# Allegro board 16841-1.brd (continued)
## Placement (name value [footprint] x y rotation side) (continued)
C7810  SC1U50V3KX-GP  [C603H32]  165.25 103.59 90 top
C7811  SC1U50V3KX-GP  [C603H32]  165.25 105.62 90 top
C7812  SC1U50V3KX-GP  [C603H32]  160.42 121.5 180 top
C7813  SC10U6D3V3MX-GP  [C603H38]  169.06 112.51 270 top
C7814  SC1U50V3KX-GP  [C603H32]  169.06 107.18 270 top
C7815  SCD1U25V2KX-GP  [C402H22]  165.25 108.67 90 top
C7816  SCD1U25V2KX-GP  [C402H22]  185.19 113.5 90 top
C7817  SCD1U25V2KX-GP  [C402H22]  184.81 114.64 0 top
C7818  SCD1U25V2KX-GP  [C402H22]  149.25 119.59 180 top
C7819  SCD1U25V2KX-GP  [C402H22]  164.99 116.17 90 top
C7820  SCD1U25V2KX-GP  [C402H22]  169.06 106.16 270 top
C7821  SCD1U25V2KX-GP  [C402H22]  170.07 115.91 270 top
C7822  SCD1U25V2KX-GP  [C402H22]  169.06 104.13 270 top
C7823  SCD1U25V2KX-GP  [C402H22]  165.25 102.58 90 top
C7824  SCD1U25V2KX-GP  [C402H22]  165.25 104.61 90 top
C7825  SCD1U25V2KX-GP  [C402H22]  165.25 106.64 90 top
C7826  SC820P50V2KX-1GP  [C402H22]  181.5 119.72 0 bottom
C7901  SCD01U50V2KX-1DLGP  [C402H22]  145.82 115.02 0 top
C7902  SC820P50V2KX-1GP  [C402H22]  147.33 110.28 270 top
C7903  SC820P50V2KX-1GP  [C402H22]  153.64 120.56 270 top
C7904  SC1U50V3KX-GP  [C603H32]  147.59 117.82 270 top
C7905  SC1U50V3KX-GP  [C603H32]  169.06 114.8 270 top
C7906  SC1U50V3KX-GP  [C603H32]  165.5 115.15 90 top
C7907  SC10U6D3V3MX-GP  [C603H38]  147.52 106.97 270 top
C7908  SC820P50V2KX-1GP  [C402H22]  156.92 120.57 90 top
C7909  SCD1U25V2KX-GP  [C402H22]  169.06 108.2 270 top
C7910  SCD1U25V2KX-GP  [C402H22]  147.59 118.84 270 top
C7911  SCD1U25V2KX-GP  [C402H22]  170.07 116.67 270 top
C7912  SCD1U25V2KX-GP  [C402H22]  169.06 113.78 270 top
C7913  SCD1U25V2KX-GP  [C402H22]  169.06 111.5 270 top
C7914  SCD1U25V2KX-GP  [C402H22]  147.52 105.96 270 top
C7915  SC1U50V3KX-GP  [C603H32]  165.25 112.99 90 top
C7916  SC1U50V3KX-GP  [C603H32]  188.36 108.29 90 top
C7917  SC1U50V3KX-GP  [C603H32]  190.27 107.3 180 top
C7918  SC10U6D3V3MX-GP  [C603H38]  165.25 107.66 90 top
C7919  SC1U50V3KX-GP  [C603H32]  191.54 107.3 180 top
C7920  SCD1U25V2KX-GP  [C402H22]  165.25 114.01 90 top
C7921  SCD1U25V2KX-GP  [C402H22]  165.25 111.97 90 top
C7922  SCD1U25V2KX-GP  [C402H22]  167.28 100.8 180 top
C7923  SCD1U25V2KX-GP  [C402H22]  188.36 107.28 90 top
C7924  SC1U50V3KX-GP  [C603H32]  192.81 107.3 180 top
C7925  SCD1U25V2KX-GP  [C402H22]  188.36 105.75 90 top
C7926  SCD1U25V2KX-GP  [C402H22]  188.36 106.51 90 top
C8301  SC10U25V5KX-DL-GP  [C805H58]  182.01 73.37 270 bottom
C8302  SC470P50V2KX-3GP  [C402H22]  180.61 76.41 90 bottom
C8304  SC10U25V5KX-DL-GP  [C805H58]  182.14 78.7 270 bottom
C8305  SC1U10V2KX-1GP  [C402H22]  184.42 78.19 90 bottom
C8306  SC470P50V2KX-3GP  [C402H22]  180.61 75.65 90 bottom
C8307  SC1U10V2KX-1GP  [C402H22]  184.3 73.87 90 bottom
C8308  SCD1U16V2KX-3GP  [C402H22]  126.77 123.53 90 bottom
C8309  SC1U10V2KX-1GP  [C402H22]  126.77 122.01 90 bottom
C8310  SC1U10V2KX-1GP  [C402H22]  127.15 115.66 90 bottom
C9101  SC2200P50V2KX-2GP  [C402H22]  222.02 35.27 270 top
C9102  SCD1U16V2KX-3GP  [C402H22]  222.02 36.03 270 top
C9104  SC2200P50V2KX-2GP  [C402H22]  222.02 36.79 270 top
C9105  SC4D7U6D3V3KX-GP  [C603H36]  212.49 38.57 0 top
C9106  SC4D7U6D3V3KX-GP  [C603H36]  219.86 33.11 180 top
C9113  SCD1U16V2KX-3GP  [C402H22]  220.87 32.98 180 top
C9114  SC4D7U6D3V3KX-GP  [C603H36]  217.83 38.06 180 top
CCGDB1  SPD-CON6-S-GP  [JD11P8204-061]  26.94 53.81 90 bottom
CPU1  SKYLAKE-U-GP  [BGA1356M4224-U2H52]  119.4 55.2 270 bottom
D502  AZ5725-01FDR7G-GP  [SOD882-10D6-1H20]  105.73 17 0 bottom
D1701  RB751V-40H-GP  [SOD323AKH38]  87.14 18.38 270 top
D2401  BAT54C-12-GP  [SOT-23-9H44]  137.21 16.72 90 top
D2402  RB751V-40H-GP  [SOD323AKH38]  141.24 27.39 0 top
D2403  RB751V-40H-GP  [SOD323AKH38]  158.01 25.87 90 top
D2501  BAS40C-2-GP  [SOT-23-9H44]  168.68 5.04 90 top
D2601  RB551V30-GP  [SOD323AKH38]  204.36 74.13 90 top
D2702  BAT54C-12-GP  [SOT-23-9H44]  15.26 12.66 0 top
D3701  SBA0520Q-R1-00001-GP-U  [D1006-0305AK-UH22]  43.45 31.33 90 top
D3702  SBA0520Q-R1-00001-GP-U  [D1006-0305AK-UH22]  43.45 32.85 90 top
D4001  LBAS16LT1G-GP  [SOT23-2D4-312H44]  165.5 8.85 0 top
D4002  RB751V-40H-GP  [SOD323AKH38]  150.77 21.17 90 bottom
D4003  RB751V-40H-GP  [SOD323AKH38]  157.37 21.8 0 bottom
D4004  RB751V-40H-GP  [SOD323AKH38]  78.76 5.7 90 top
D4005  RB751V-40H-GP  [SOD323AKH38]  204.11 48.98 0 top
D4304  LBAV99LT1G-1-GP  [SOT23-2D4-312H44]  197.51 17.61 0 bottom
D4305  LBAV99LT1G-1-GP  [SOT23-2D4-312H44]  200.17 15.71 270 bottom
D4306  LBAV99LT1G-1-GP  [SOT23-2D4-312H44]  200.17 12.28 270 bottom
D5501  BAT54C-12-GP  [SOT-23-9H44]  96.54 91.65 0 bottom
D5502  BAT54C-12-GP  [SOT-23-9H44]  91.59 91.02 0 bottom
D5701  LBAW56LT1G-GP  [SOT23-2D4-312H44]  14.63 71.72 0 bottom
D7001  BAT54A-7-F-2-GP  [SOT23-2D4-312H48]  209.95 55.87 90 top
D7301  BAT54A-11-GP  [SOT-23-9H44]  147.47 68.16 90 bottom
D8301  BAT54C-12-GP  [SOT-23-9H44]  210.59 65.24 90 top
DB1  DM-ACES-CON14-5-GP-01  [DM-87212-1400N-01]  167.91 2.5 0 bottom
DBEC1  ACES-CON6-58-GP  [50696-00601-001]  181.88 3.64 270 bottom
DCIN1  ACES-CON8-13-GP-U2  [50224-0080N-W02-U]  19.05 94.6 0 bottom
DM1  DDR4-260P-65-GP  [ADDR0206-P013A]  65.8 53.2 270 bottom
DM2  DDR4-260P-64-GP  [ADDR0205-P012A]  52.75 53.2 90 bottom
EC401  AZ5725-01FDR7G-GP  [SOD882-10D6-1H20]  136.16 74 270 bottom
EC1001  SCD1U25V2KX-L-GP  [C402H22]  120.24 48.98 0 top
EC1002  SCD1U25V2KX-L-GP  [C402H22]  143.71 50.76 270 top
EC1003  SCD1U25V2KX-L-GP  [C402H22]  142.77 52.03 0 top
EC1004  SCD1U25V2KX-L-GP  [C402H22]  142.01 52.03 0 top
EC1005  SC1U10V2KX-1GP  [C402H22]  114.57 72.02 270 top
EC1006  SCD1U25V2KX-L-GP  [C402H22]  113.56 76.03 270 top
EC1007  SCD1U25V2KX-L-GP  [C402H22]  145.44 30.44 90 bottom
EC1102  SC100P50V2JN-3DLGP  [C402H22]  96.92 65.49 180 top
EC1103  SC2D2U6D3V2MX-DL-GP  [C402H22]  56.15 85.56 180 top
EC1202  SC2D2U6D3V2MX-DL-GP  [C402H22]  72.54 38.7 90 top
EC1203  SCD1U25V2KX-GP  [C402H22]  69.36 35.52 270 top
EC1302  SC2D2U6D3V2MX-DL-GP  [C402H22]  46.76 86.32 90 top
EC1303  SC2D2U6D3V2MX-DL-GP  [C402H22]  69.74 23.96 0 top
EC1701  AZ5725-01FDR7G-GP  [SOD882-10D6-1H20]  125.45 82.13 180 bottom
EC1702  AZ5725-01FDR7G-GP  [SOD882-10D6-1H20]  138.17 36.2 270 bottom
EC1703  AZ5725-01FDR7G-GP  [SOD882-10D6-1H20]  117.88 19.01 270 bottom
EC1704  AZ5725-01FDR7G-GP  [SOD882-10D6-1H20]  108.2 16.7 0 bottom
EC1705  AZ5725-01FDR7G-GP  [SOD882-10D6-1H20]  91.26 10.43 270 top
EC1706  SC1KP50V2KX-1GP  [C402H22]  119.27 35.9 180 top
EC1707  SCD1U16V2KX-3GP  [C402H22]  112.16 16.47 180 bottom
EC1708  AZ5725-01FDR7G-GP  [SOD882-10D6-1H20]  125.37 84.16 0 bottom
EC1709  AZ5725-01FDR7G-GP  [SOD882-10D6-1H20]  122.45 84.67 270 bottom
EC1710  SC2D2U6D3V2MX-DL-GP  [C402H22]  103.91 14.49 270 bottom
EC1712  SCD1U16V2KX-3GP  [C402H22]  89.81 17.23 90 top
EC1801  SC10P50V2JN-4GP  [C402H22]  94.13 36.16 180 top
EC1803  SC4D7P50V2BN-GP  [C402H22]  97.81 49.74 90 top
EC1806  SCD1U16V2KX-3GP  [C402H22]  74.06 20.61 0 top
EC1807  SCD1U16V2KX-3GP  [C402H22]  70.96 21.8 270 top
EC1808  SCD1U16V2KX-3GP  [C402H22]  75.84 26.76 180 top
EC1901  SC10P50V2JN-4GP  [C402H22]  93.87 46.19 0 top
EC1902  SCD1U16V2KX-3GP  [C402H22]  97.94 44.54 270 top
EC1903  SCD1U25V2KX-GP  [C402H22]  94.64 47.08 0 top
EC2002  SC1KP50V2KX-1DLGP  [C402H22]  121.51 34.86 90 top
EC2101  SCD1U25V2KX-GP  [C402H22]  97.56 18.38 90 bottom
EC2501  SC4D7P50V2BN-GP  [C402H22]  171.85 20.15 270 bottom
EC2502  SC4D7P50V2BN-GP  [C402H22]  158.39 17.87 90 bottom
EC2503  SC10P50V2JN-4GP  [C402H22]  171.85 17.87 270 bottom
EC2601  SC10P50V2JN-4GP  [C402H22]  207.41 73.75 270 top
EC2602  SC10P50V2JN-4GP  [C402H22]  208.94 73.75 90 top
EC2708  SC10P50V2JN-4DLGP  [C402H22]  31.64 19.77 0 top
EC2709  SC1KP50V2KX-1DLGP  [C402H22]  16.91 20.66 270 top
EC2710  SC1KP50V2KX-1DLGP  [C402H22]  20.13 23.13 180 top
EC2711  SC1KP50V2KX-1DLGP  [C402H22]  22.52 13.02 0 bottom
EC2712  SCD1U25V2KX-1-DL-GP  [C402H22]  21.74 7.38 0 top
EC2713  SCD1U25V2KX-1-DL-GP  [C402H22]  13.23 16.24 270 top
EC2714  SCD1U25V2KX-1-DL-GP  [C402H22]  8.66 14.82 180 top
EC2901  SC1KP50V2KX-1DLGP  [C402H22]  33.04 8.22 90 top
EC2902  SC1KP50V2KX-1DLGP  [C402H22]  28.6 10.63 180 top
EC2903  SC1KP50V2KX-1DLGP  [C402H22]  34.82 5.55 180 top
EC2904  SC1KP50V2KX-1DLGP  [C402H22]  35.07 3.01 90 top
EC2905  SC100P50V2JN-3DLGP  [C402H22]  20.09 13.04 180 bottom
EC2906  SC100P50V2JN-3DLGP  [C402H22]  17.88 17.11 270 bottom
EC2907  SC680P50V2KX-2DLGP  [C402H22]  17.88 17.92 270 bottom
EC2908  SC680P50V2KX-2DLGP  [C402H22]  17.88 18.73 270 bottom
EC3601  SCD1U25V2KX-GP  [C402H22]  20.59 48.98 180 bottom
EC3602  SCD1U25V2KX-GP  [C402H22]  16.91 23.23 180 bottom
EC4301  SC10U25V5KX-DL-GP  [C805H58]  19.32 90.64 270 top
EC4302  SCD1U25V2KX-GP  [C402H22]  19.45 92.04 270 top
EC4306  SC10P50V2JN-4GP  [C402H22]  196.24 15.84 270 bottom
EC4307  SC1KP50V2KX-1DLGP  [C402H22]  170.71 25.36 90 bottom
EC4308  SCD1U50V3KX-GP  [C603H36]  170.71 26.63 90 bottom
EC4309  SC10P50V2JN-4GP  [C402H22]  197.51 13.42 180 bottom
EC4310  SC10P50V2JN-4GP  [C402H22]  197.51 14.95 0 bottom
EC4311  SCD1U25V2KX-GP  [C402H22]  21.23 96.48 180 top
EC4312  SC1KP50V2KX-1DLGP  [C402H22]  19.45 93.56 270 top
EC4313  SCD1U25V2KX-GP  [C402H22]  19.45 92.8 270 top
EC5501  SC6D8P50V2CN-DL-GP  [C402H22]  96.03 94.58 90 bottom
EC5502  SCD1U25V2KX-GP  [C402H22]  108 91.73 180 bottom
EC5503  SC22P50V2JN-4GP  [C402H22]  113.39 100.73 90 top
EC5504  SC33P50V2JN-3DLGP  [C402H22]  111.87 100.73 270 top
EC5505  SC33P50V2JN-3GP  [C402H22]  68.35 101.69 180 top
EC6401  SC220P50V2KX-3GP  [C402H22]  56.85 5.17 90 top
EC6402  SC220P50V2KX-3GP  [C402H22]  55.33 5.17 270 top
EC6501  SC33P50V2JN-3GP  [C402H22]  153.18 8.6 180 bottom
EC6502  SC33P50V2JN-3GP  [C402H22]  152.67 10.88 0 bottom
EC6503  SC33P50V2JN-3GP  [C402H22]  126 18.76 0 bottom
EC6504  SC33P50V2JN-3GP  [C402H22]  121.05 19.52 0 bottom
EC6505  SC10P50V2JN-4GP  [C402H22]  93.72 14.21 180 bottom
EC6506  SC10P50V2JN-4GP  [C402H22]  95.78 14.44 270 bottom
EC6507  SC10P50V2JN-4GP  [C402H22]  146.71 26.38 0 bottom
EC6601  SC33P50V2JN-3GP  [C402H22]  205.25 58 270 top
EC6602  SC33P50V2JN-3GP  [C402H22]  205.25 57.24 270 top
EC6603  SC33P50V2JN-3GP  [C402H22]  205.25 58.76 270 top
EC8901  SCD1U25V2KX-GP  [C402H22]  20.92 23.13 180 top
EC8902  SCD1U25V2KX-GP  [C402H22]  14.88 7.33 225 bottom
EC8903  SCD1U25V2KX-GP  [C402H22]  17.06 20.48 180 bottom
EC8904  SCD1U25V2KX-GP  [C402H22]  21.79 15.81 270 bottom
EC8905  SC1KP50V2KX-1GP  [C402H22]  117.88 99.27 0 top
EC8906  SC2200P50V2KX-2GP  [C402H22]  197.25 75.78 0 bottom
EC8907  SC1KP50V2KX-1DLGP  [C402H22]  81.3 102.2 270 top
EC8908  SCD1U25V2KX-GP  [C402H22]  120.92 98.26 270 top
EC8909  SCD1U25V2KX-GP  [C402H22]  64.03 97.88 270 top
EC8910  SC1KP50V2KX-1DLGP  [C402H22]  227.12 28.54 270 top
EC8911  SCD1U25V2KX-GP  [C402H22]  32.79 17.49 0 top
EC8912  SCD1U25V2KX-GP  [C402H22]  54.5 96.86 0 bottom
EC8913  SCD1U25V2KX-GP  [C402H22]  25.8 86.07 0 top
EC8914  SCD1U25V2KX-GP  [C402H22]  22.12 36.28 270 top
EC8915  SCD1U25V2KX-GP  [C402H22]  201.57 51.4 90 top
EC8916  SC1KP50V2KX-1DLGP  [C402H22]  25.04 3.39 90 top
EC8917  SCD1U25V2KX-GP  [C402H22]  14.5 84.29 90 top
EC8918  SC1KP50V2KX-1GP  [C402H22]  49.17 84.03 90 top
EC8919  SC1KP50V2KX-1DLGP  [C402H22]  62.12 84.16 90 top
EC8920  SC100P50V2JN-3DLGP  [C402H22]  51.33 73.87 0 top
EC8921  SCD1U25V2KX-GP  [C402H22]  94.76 55.21 0 top
EC8922  SC1KP50V2KX-1DLGP  [C402H22]  51.33 29.81 90 top
EC8923  SCD1U25V2KX-GP  [C402H22]  56.54 78.57 270 top
EC8924  SCD1U25V2KX-GP  [C402H22]  112.03 51.65 90 top
EC8925  SCD1U25V2KX-GP  [C402H22]  69.36 77.05 270 top
EC8927  SC1KP50V2KX-1GP  [C402H22]  120.16 100.42 180 bottom
EC8928  SC1KP50V2KX-1GP  [C402H22]  167.28 50.76 270 top
EC8929  SC1KP50V2KX-1GP  [C402H22]  167.79 56.09 0 bottom
EC8933  SC2200P50V2KX-2GP  [C402H22]  72.79 49.11 0 top
EC8934  SC100P50V2JN-3DLGP  [C402H22]  64.16 23.96 0 top
EC8935  SC2200P50V2KX-2GP  [C402H22]  62 29.55 90 top
EC8936  SCD1U25V2KX-GP  [C402H22]  62.12 40.47 90 top
EC8937  SC1KP50V2KX-1DLGP  [C402H22]  83.59 51.4 0 top
EC8938  SCD1U25V2KX-GP  [C402H22]  54.17 30.85 90 top
EC8939  SC1KP50V2KX-1GP  [C402H22]  99.94 88.38 180 bottom
EC8940  SC1KP50V2KX-1GP  [C402H22]  39.01 2.25 90 bottom
EC8941  SC1KP50V2KX-1DLGP  [C402H22]  111.15 12.79 90 top
EC8942  SC1KP50V2KX-1GP  [C402H22]  26.44 34.38 0 top
EC8943  SC1KP50V2KX-1GP  [C402H22]  80.79 3.38 90 top
EC8944  SC1KP50V2KX-1GP  [C402H22]  184.55 58.86 90 top
EC8945  SC1KP50V2KX-1DLGP  [C402H22]  197.4 51.68 270 top
EC8946  SC1KP50V2KX-1GP  [C402H22]  67.08 4.18 90 top
EC8947  SC1KP50V2KX-1DLGP  [C402H22]  51.48 17.74 270 top
EC8948  SC1KP50V2KX-1GP  [C402H22]  44.98 28.41 0 top
EC8949  SC1KP50V2KX-1GP  [C402H22]  21.74 40.6 90 top
EC8951  SCD1U25V2KX-GP  [C402H22]  167.28 40.22 270 top
EC8952  SCD1U25V2KX-GP  [C402H22]  168.8 55.97 0 bottom
EC8953  SCD1U25V2KX-GP  [C402H22]  198.01 75.78 0 bottom
EC8954  SCD1U25V2KX-GP  [C402H22]  144.17 113.14 270 bottom
EC8955  SCD1U25V2KX-GP  [C402H22]  119.78 99.27 0 top
EC8956  SCD1U25V2KX-GP  [C402H22]  166.52 74.26 180 top
EC8957  SC1KP50V2KX-1DLGP  [C402H22]  146.83 74.89 270 top
EC8958  SCD1U25V2KX-GP  [C402H22]  167.28 48.86 270 top
EC8959  SC1KP50V2KX-1DLGP  [C402H22]  122.96 106.64 270 top
EC8960  SC1KP50V2KX-1GP  [C402H22]  117.88 90.26 270 top
EC8961  SC1KP50V2KX-1DLGP  [C402H22]  188.11 44.79 270 top
EC8962  SC1KP50V2KX-1GP  [C402H22]  176.8 59.4 180 top
EC8963  SC1KP50V2KX-1DLGP  [C402H22]  98.19 87.08 0 top
EC8964  SC1KP50V2KX-1GP  [C402H22]  85.36 87.08 0 top
EC8965  SC1KP50V2KX-1GP  [C402H22]  61.11 95.59 180 top
EC8966  SC1KP50V2KX-1GP  [C402H22]  50.19 95.59 180 top
EC8967  SC1KP50V2KX-1DLGP  [C402H22]  34.06 96.99 180 top
EC8968  SC1KP50V2KX-1GP  [C402H22]  127.02 89.75 90 bottom
EC8969  SC1KP50V2KX-1GP  [C402H22]  141.24 52.03 0 top
EC8970  SC1KP50V2KX-1GP  [C402H22]  140.48 52.03 0 top
EC8971  SC1KP50V2KX-1GP  [C402H22]  118.13 49.24 0 top
EC8972  SC1KP50V2KX-1GP  [C402H22]  78 10.76 0 top
EC8973  SC1KP50V2KX-1GP  [C402H22]  77.24 10.76 0 top
EC8974  SC1KP50V2KX-1DLGP  [C402H22]  76.47 10.76 0 top
EC8975  SC1KP50V2KX-1DLGP  [C402H22]  34.28 17.08 90 top
EC8976  SC1KP50V2KX-1DLGP  [C402H22]  204.64 51.09 270 top
EC8977  SC1KP50V2KX-1DLGP  [C402H22]  186.96 74.64 90 top
EC8978  SC1KP50V2KX-1GP  [C402H22]  219.86 51.78 0 top
EC8979  SC1KP50V2KX-1DLGP  [C402H22]  167.38 10.15 90 top
EC8980  SC1KP50V2KX-1GP  [C402H22]  205.76 65.62 180 top
EC8981  SC1KP50V2KX-1GP  [C402H22]  207.64 56.22 270 top
EC8982  SC1KP50V2KX-1GP  [C402H22]  201.82 12.28 270 bottom
EC8983  SC1KP50V2KX-1DLGP  [C402H22]  69.11 3.39 0 top
EC8984  SC1KP50V2KX-1DLGP  [C402H22]  230.27 8.72 90 top
EC8985  SC1KP50V2KX-1GP  [C402H22]  191.92 4.28 180 top
EC8986  SC1KP50V2KX-1GP  [C402H22]  63.77 96.1 270 top
EC8987  SC1KP50V2KX-1DLGP  [C402H22]  201.06 46.95 270 top
EC8988  SC1KP50V2KX-1DLGP  [C402H22]  67.97 3.39 90 top
EC8989  SC1KP50V2KX-1GP  [C402H22]  15.39 82.69 90 top
EC8992  SC1KP50V2KX-1GP  [C402H22]  24.02 39.84 270 top
EC8993  SC1KP50V2KX-1GP  [C402H22]  151.91 14.69 270 bottom
EC8994  SC1KP50V2KX-1DLGP  [C402H22]  197.25 47.97 0 top
EC8995  SC1KP50V2KX-1GP  [C402H22]  206.4 55.97 180 top
EC8996  SC1KP50V2KX-1DLGP  [C402H22]  167.41 11.52 90 top
EC8997  SC1KP50V2KX-1GP  [C402H22]  113.3 13.93 0 bottom
EC8998  SC1KP50V2KX-1GP  [C402H22]  68.09 5.29 0 top
EC8999  SC1KP50V2KX-1DLGP  [C402H22]  34.95 12.28 270 bottom
ED1217  AZ5725-01FDR7G-GP  [SOD882-10D6-1H20]  47.06 60.92 180 top
ED1302  AZ5725-01FDR7G-GP  [SOD882-10D6-1H20]  46.17 60.92 180 top
ED2403  AZ5725-01FDR7G-GP  [SOD882-10D6-1H20]  139.72 14.44 90 top
ED2901  AZ5125-02S-R7G-GP  [SOT23-2D4-312H46]  17.55 9.49 0 bottom
ED2902  AZ5125-02S-R7G-GP  [SOT23-2D4-312H46]  14.17 15.2 270 bottom
ED2903  AZ5125-02S-R7G-GP  [SOT23-2D4-312H46]  17.17 9.49 180 top
ED3601  L05ESDL5V0NA-4-GP  [SLP2510P8-1H22]  18.31 50.13 90 top
ED3602  AZC099-04S-1-GP  [SOT-6H58]  17.42 50 90 bottom
ED3603  L05ESDL5V0NA-4-GP  [SLP2510P8-1H22]  18.31 26.88 90 top
ED3604  AZC099-04S-1-GP  [SOT-6H58]  18.31 25.36 270 bottom
ED3801  L05ESDL5V0NA-4-GP  [SLP2510P8-1H22]  15.26 90.38 180 top
ED3802  L05ESDL5V0NA-4-GP  [SLP2510P8-1H22]  10.18 94.29 270 bottom
ED3803  AZ5315-02F-GP  [SOT883-1D0-321H20]  14.75 97.88 180 top
ED3804  AZ5315-02F-GP  [SOT883-1D0-321H20]  9.8 91.15 180 top
ED3805  AZ5315-02F-GP  [SOT883-1D0-321H20]  9.93 93.31 0 top
ED3806  AZ5315-02F-GP  [SOT883-1D0-321H20]  11.2 90.13 0 top
ED5501  AZC099-04S-1-GP  [SOT-6H58]  117.34 92.84 180 bottom
ED5502  AZ5725-01FDR7G-GP  [SOD882-10D6-1H20]  76.73 97.12 0 top
ED5701  L05ESDL5V0NA-4-GP  [SLP2510P8-1H22]  14.75 68.79 90 top
ED5702  L05ESDL5V0NA-4-GP  [SLP2510P8-1H22]  14.6 72.17 90 top
ED6001  L05ESDL5V0NA-4-GP  [SLP2510P8-1H22]  207.92 9.74 270 bottom
ED6301  L05ESDL5V0NA-4-GP  [SLP2510P8-1H22]  213.46 16.64 90 bottom
ED6401  PESD5V0S1BB-GP-U  [SOD-523-2H26]  57.61 7.96 90 top
ED6402  PESD5V0S1BB-GP-U  [SOD-523-2H26]  54.82 7.96 270 top
ED6601  AZC099-04S-1-GP  [SOT-6H58]  202.46 45.68 180 bottom
ED6602  L05ESDL5V0NA-4-GP  [SLP2510P8-1H22]  203.22 41.24 90 bottom
EL3602  COIL-90OHM-100MHZ-5-GP  [L125100-4P-4H24]  19.71 46.95 90 bottom
EL3603  COIL-90OHM-100MHZ-5-GP  [L125100-4P-4H24]  21.1 26 180 bottom
EL3801  COIL-90OHM-100MHZ-5-GP  [L125100-4P-4H24]  11.58 91.65 180 top
EL3802  COIL-90OHM-100MHZ-5-GP  [L125100-4P-4H24]  11.58 93.31 180 top
EL4301  -  [0R0805-PAD]  21.66 89.6 0 top
EL4302  -  [0R0805-PAD]  23.46 89.6 0 top
EL4303  -  [0R0805-PAD]  18.94 96.1 90 top
EL4304  -  [0R0805-PAD]  16.53 97.12 180 top
EL5501  COIL-90OHM-100MHZ-5-GP  [L125100-4P-4H24]  118.13 89.9 90 bottom
EL6601  COIL-90OHM-100MHZ-5-GP  [L125100-4P-4H24]  210.18 45.14 0 top
EL6603  COIL-90OHM-100MHZ-5-GP  [L125100-4P-4H24]  210.21 43.6 0 top
ER5744  180R2J-1-GP  [R402H16]  16.02 67.78 180 top
ER5745  180R2J-1-GP  [R402H16]  15.9 73.04 0 top
ER5758  180R2J-1-GP  [R402H16]  16.02 69.56 180 top
ER5759  180R2J-1-GP  [R402H16]  15.9 71.33 180 top
F5502  POLYSW-D5A6V-1-GP  [POLYSW-2114H50]  110.51 93.94 90 bottom
F5503  POLYSW-1D1A24V-GP-U  [POLYSW-4633-UH43]  87.14 97.5 270 top
F5701  POLYSW-1D1A6V-9-GP-U  [POLYSW-2114H30]  14.65 80.83 0 top
F6501  POLYSW-D5A6V-1-GP  [POLYSW-2114H50]  99.99 14.92 180 bottom
FAN1  ACES-CON4-29-GP  [50224-0040N-001]  205.1 72.1 0 bottom
G1801  GAP-OPEN  [CON2O-U]  70.76 15.2 0 bottom
GPU1  N16S-GM-S-A2-GP  [BGA595M23H83]  162.25 83.4 90 bottom
H1  HOLE335R178-GP  [HOLE335R178]  106.4 83.6 180 bottom
H2  HOLE335R178-GP  [HOLE335R178]  132.4 83.6 180 bottom
H3  HOLE335R178-GP  [HOLE335R178]  106.4 25.8 180 bottom
H4  HOLE335R178-GP  [HOLE335R178]  132.4 25.8 180 bottom
H5  HOLE335R178-GP  [HOLE335R178]  184.24 84.17 180 bottom
H6  HOLE335R178-GP  [HOLE335R178]  146.16 98.4 180 bottom
H7  HOLE335R178-GP  [HOLE335R178]  163.02 61.41 180 bottom
H8  HOLE335R178-GP  [HOLE335R178]  29.3 99.1 180 bottom
H11  HOLE335R178-GP  [HOLE335R178]  130.4 4.3 180 bottom
H12  HOLE335R178-GP  [HOLE335R178]  176.8 48.86 180 bottom
H14  HOLE335R178-GP  [HOLE335R178]  200.05 4.6 180 bottom
HDA27  ALC3254-CG-GP  [QFN48J6-G465H40]  23.9 15.07 270 top
HDD1  ACES-CON20-28-GP  [50406-02071-001]  223.55 3.9 0 bottom
HDMI2  SKT-HDMI23-172-GP  [SKT-HDMI23-187137-1]  3.55 72.1 90 bottom
HPMIC1  AUDIO-JK505-GP  [AJ3R1S-Y050-412]  2.6 7.1 90 bottom
HS2  STF217R115H101-2-GP  [STF217R115H101]  8.65 84.6 180 bottom
IOBD1  IPEX-CON60-GP-U  [20525-060E-02-U]  208.55 48.6 270 bottom
KB1  PTWO-CON30-18-GP  [196528-30041-3]  76.82 10 180 bottom
KBBL2  ACES-CON4-90-GP-U  [50698-00401-W01-U]  98.8 6.6 180 bottom
KBC24  MEC1416-NU-D0-GP  [TQFP128-2H48]  150.64 15.58 270 top
L3801  BLM15AX221SN1D-GP  [L402H22]  31.01 50.63 90 top
L5801  BLM18KG331SN1D-GP  [L603H38]  29.23 75.02 270 top
L5802  BLM18KG331SN1D-GP  [L603H38]  29.48 64.73 180 top
L5803  BLM18KG331SN1D-GP  [L603H38]  34.56 64.73 180 top
L5804  BLM18KG331SN1D-GP  [L603H38]  32.02 64.73 180 top
L5805  BLM18KG331SN1D-GP  [L603H38]  26.94 64.73 180 top
L7301  HCB1608KF121T30-GP  [L1608-UH38]  145.44 85.81 90 bottom
L7501  MHC1608S300QBP-GP  [L603H38]  145.44 87.08 90 bottom
L7601  MHC1608S300QBP-GP  [L603H38]  164.74 68.67 0 bottom
L7602  MCB1608S181FBP-GP  [L603H38]  163.47 68.67 0 bottom
LCD1  STAR-CON50-2-GP-U  [300E50-1030RA-G4]  102.6 99.3 0 bottom
LEDCN1  ACES-CON4-66-GP  [50524-00401-001]  56.2 4.6 180 bottom
NOREF  -  []  81.17 38.26 0 top
NOREF#2  -  [unnamed#2]  -3.85 -2.19 0 top
NOREF#3  *  [unnamed#2]  159.94 29.76 0 top
NOREF#4  *  [unnamed#2]  226.69 6.95 0 top
NOREF#5  *  [unnamed#2]  6.89 -3.35 0 top
NOREF#6  *  [unnamed#2]  182.77 100.7 0 top
NOREF#7  -  []  -6.71 130.39 270 top
NOREF#8  -  [unnamed#2]  209.97 -2.68 0 top
NOREF#9  *  [unnamed#2]  124.07 7.02 0 top
NOREF#10  *  [unnamed#2]  38.76 13.04 0 top
NOREF#11  -  []  0.15 159.47 90 top
NOREF#12  -  [unnamed#2]  7.9 37.35 0 top
NOREF#13  *  [unnamed#2]  12.16 81.34 0 top
NOREF#14  -  [unnamed#2]  195.85 95.31 0 top
NOREF#15  -  []  11.55 118.69 180 top
NOREF#16  -  [unnamed#2]  234.99 235.59 0 top
NOREF#17  *  [unnamed#2]  15.29 37.91 0 top
NOREF#18  -  []  238.8 83.3 0 top
NOREF#19  -  []  219.59 114.71 0 top
NOREF#20  -  [unnamed#2]  223.51 82.69 0 top
NOREF#21  -  [unnamed#2]  31.97 111.01 0 top
NOREF#22  -  []  -1.25 -18.2 0 top
NOREF#23  -  [unnamed#2]  225.45 37.3 0 top
NOREF#24  -  []  -1.25 -18.2 0 top
NOREF#25  -  [unnamed#2]  225.64 32.6 0 top
NOREF#26  -  [unnamed#2]  7.63 150.71 0 top
NOREF#27  -  []  177.51 140.77 180 top
NOREF#28  -  [unnamed#2]  10.55 97.85 90 top
NOREF#29  *  [unnamed#2]  21.84 59.07 0 top
NOREF#30  -  []  -1.25 -18.2 0 top
NOREF#31  -  [unnamed#2]  20.72 98.89 0 top
NOREF#32  -  [unnamed#2]  199.17 122.39 0 top
NOREF#33  -  []  85.11 75.65 0 top
NOREF#34  -  [unnamed#2]  224.1 236.67 0 top
NOREF#35  *  [unnamed#2]  223.17 -3.14 0 top
NOREF#36  *  [unnamed#2]  27.71 44.41 0 top
NOREF#37  -  [unnamed#2]  21.33 236.02 0 top
NOREF#38  *  [unnamed#2]  229.5 237.16 0 top
NOREF#39  *  [unnamed#2]  144.75 123.25 0 top
NOREF#40  -  []  53.63 92.63 0 top
NOREF#41  -  []  238.02 103.47 90 top
NOREF#42  -  []  168.55 120.99 0 top
NOREF#43  *  [unnamed#2]  229.5 237.16 180 bottom
NOREF#44  *  [unnamed#2]  167.81 121.4 180 bottom
NOREF#45  *  [unnamed#2]  58.24 92.87 180 bottom
NOREF#46  *  [unnamed#2]  20.19 19.6 180 bottom
NOREF#47  *  [unnamed#2]  166.69 100.52 180 bottom
NOREF#48  *  [unnamed#2]  210.08 12.36 180 bottom
NOREF#49  *  [unnamed#2]  142.95 76.69 180 bottom
NOREF#50  -  []  78.25 31.96 180 bottom
NOREF#51  *  [unnamed#2]  142.72 119.26 180 bottom
NOREF#52  *  [unnamed#2]  114.45 89.6 180 bottom
NOREF#53  -  []  171.88 120.59 180 bottom
NOREF#54  *  [unnamed#2]  190.63 99.97 180 bottom
NOREF#55  *  [unnamed#2]  223.17 -3.14 180 bottom
NOREF#56  *  [unnamed#2]  90.77 82.74 180 bottom
NOREF#57  -  []  3.07 173.82 270 bottom
NOREF#58  *  [unnamed#2]  94.3 25.16 180 bottom
NOREF#59  *  [unnamed#2]  6.89 -3.35 180 bottom
NOREF#60  *  [unnamed#2]  222.4 37.12 180 bottom
PC1001  SC22U6D3V3MX-1-DL-GP  [C603H40]  143.91 64.6 0 bottom
PC1002  SC22U6D3V3MX-1-DL-GP  [C603H40]  118.13 61.86 0 top
PC1003  SC22U6D3V3MX-1-DL-GP  [C603H40]  143.66 50.13 90 bottom
PC1004  SC22U6D3V3MX-1-DL-GP  [C603H40]  143.78 44.66 270 top
PC1005  SC22U6D3V3MX-1-DL-GP  [C603H40]  126.49 55.08 0 top
PC1006  SC22U6D3V3MX-1-DL-GP  [C603H40]  119.4 58.76 180 top
PC1007  SC22U6D3V3MX-1-DL-GP  [C603H40]  120.67 58.76 180 top
PC1008  SC22U6D3V3MX-1-DL-GP  [C603H40]  120.67 61.86 0 top
PC1009  SC22U6D3V3MX-1-DL-GP  [C603H40]  143.78 47.2 270 top
PC1010  SC22U6D3V3MX-1-DL-GP  [C603H40]  118.08 54.59 0 top
PC1011  SC22U6D3V3MX-1-DL-GP  [C603H40]  119.35 54.59 0 top
PC1012  SC22U6D3V3MX-1-DL-GP  [C603H40]  120.62 54.59 0 top
PC1013  SC22U6D3V3MX-1-DL-GP  [C603H40]  121.89 54.59 0 top
PC1014  SC22U6D3V3MX-1-DL-GP  [C603H40]  123.16 54.59 0 top
PC1015  SC22U6D3V3MX-1-DL-GP  [C603H40]  116.86 58.76 180 top
PC1016  SC22U6D3V3MX-1-DL-GP  [C603H40]  124.43 54.59 0 top
PC1017  SC22U6D3V3MX-1-DL-GP  [C603H40]  121.94 58.76 180 top
PC1018  SC22U6D3V3MX-1-DL-GP  [C603H40]  143.66 51.4 90 bottom
PC1019  SC22U6D3V3MX-1-DL-GP  [C603H40]  143.66 47.59 90 bottom
PC1020  SC22U6D3V3MX-1-DL-GP  [C603H40]  116.73 54.57 0 top
PC1021  SC22U6D3V3MX-1-DL-GP  [C603H40]  119.4 61.86 0 top
PC1022  SC22U6D3V3MX-1-DL-GP  [C603H40]  143.66 41.24 90 bottom
PC1023  SC22U6D3V3MX-1-DL-GP  [C603H40]  143.66 46.32 90 bottom
PC1024  SC22U6D3V3MX-1-DL-GP  [C603H40]  121.94 61.86 0 top
PC1025  SC22U6D3V3MX-1-DL-GP  [C603H40]  118.77 52.16 180 top
PC1026  SC22U6D3V3MX-1-DL-GP  [C603H40]  143.66 48.86 90 bottom
PC1027  SC22U6D3V3MX-1-DL-GP  [C603H40]  118.13 58.76 180 top
PC1028  SC22U6D3V3MX-1-DL-GP  [C603H40]  143.66 45.05 90 bottom
PC1029  SC22U6D3V3MX-1-DL-GP  [C603H40]  120.8 52.16 180 top
PC1030  SC22U6D3V3MX-1-DL-GP  [C603H40]  122.96 52.16 180 top
PC1031  SC22U6D3V3MX-1-DL-GP  [C603H40]  143.66 43.78 90 bottom
PC1032  SC22U6D3V3MX-1-DL-GP  [C603H40]  143.66 42.51 90 bottom
PC1034  SC22U6D3V3MX-1-DL-GP  [C603H40]  143.66 39.97 90 bottom
PC1036  SC22U6D3V3MX-1-DL-GP  [C603H40]  116.86 61.86 0 top
PC1037  SC22U6D3V3MX-1-DL-GP  [C603H40]  119.91 68.16 90 top
PC1038  SC22U6D3V3MX-1-DL-GP  [C603H40]  117.88 81.11 90 bottom
PC1039  SC22U6D3V3MX-1-DL-GP  [C603H40]  144.29 59.8 180 bottom
PC1040  SC22U6D3V3MX-1-DL-GP  [C603H40]  114.83 70.45 0 top
PC1041  SC22U6D3V3MX-1-DL-GP  [C603H40]  123.21 68.29 270 top
PC1042  SC22U6D3V3MX-1-DL-GP  [C603H40]  146.45 64.6 0 bottom
PC1043  SC22U6D3V3MX-1-DL-GP  [C603H40]  119.91 65.62 90 top
PC1044  SC22U6D3V3MX-1-DL-GP  [C603H40]  114.96 74.89 270 top
PC1045  SC22U6D3V3MX-1-DL-GP  [C603H40]  138.7 64.6 0 bottom
PC1046  SC22U6D3V3MX-1-DL-GP  [C603H40]  143.02 59.8 180 bottom
PC1047  SC22U6D3V3MX-1-DL-GP  [C603H40]  119.91 66.89 90 top
PC1048  SC22U6D3V3MX-1-DL-GP  [C603H40]  123.21 67.02 270 top
PC1049  SC22U6D3V3MX-1-DL-GP  [C603H40]  123.21 69.56 270 top
PC1050  SC22U6D3V3MX-1-DL-GP  [C603H40]  116.68 65.62 270 top
PC1051  SC22U6D3V3MX-1-DL-GP  [C603H40]  147.72 64.6 0 bottom
PC1052  SC22U6D3V3MX-1-DL-GP  [C603H40]  116.68 66.89 270 top
PC1053  SC22U6D3V3MX-1-DL-GP  [C603H40]  141.75 59.8 180 bottom
PC1054  SC22U6D3V3MX-1-DL-GP  [C603H40]  123.21 65.75 270 top
PC1055  SC22U6D3V3MX-1-DL-GP  [C603H40]  140.48 59.8 180 bottom
PC1056  SC22U6D3V3MX-1-DL-GP  [C603H40]  139.21 59.8 180 bottom
PC1057  SC22U6D3V3MX-1-DL-GP  [C603H40]  141.24 64.6 0 bottom
PC1058  SC22U6D3V3MX-1-DL-GP  [C603H40]  122.19 81.88 0 bottom
PC1059  SC22U6D3V3MX-1-DL-GP  [C603H40]  116.68 69.43 270 top
PC1060  SC22U6D3V3MX-1-DL-GP  [C603H40]  117.88 82.38 90 bottom
PC1061  SC22U6D3V3MX-1-DL-GP  [C603H40]  114.96 73.62 270 top
PC1062  SC22U6D3V3MX-1-DL-GP  [C603H40]  119.91 69.43 90 top
PC1063  SC22U6D3V3MX-1-DL-GP  [C603H40]  120.92 81.88 0 bottom
PC1064  SC22U6D3V3MX-1-DL-GP  [C603H40]  148.99 64.6 0 bottom
PC1065  SC22U6D3V3MX-1-DL-GP  [C603H40]  123.46 81.88 0 bottom
PC1066  SC22U6D3V3MX-1-DL-GP  [C603H40]  116.68 68.16 270 top
PC1067  SC22U6D3V3MX-1-DL-GP  [C603H40]  142.64 64.6 0 bottom
PC1068  SC22U6D3V3MX-1-DL-GP  [C603H40]  117.88 79.84 90 bottom
PC1069  SC22U6D3V3MX-1-DL-GP  [C603H40]  145.18 64.6 0 bottom
PC1070  SC22U6D3V3MX-1-DL-GP  [C603H40]  139.97 64.6 0 bottom
PC1071  SC22U6D3V3MX-1-DL-GP  [C603H40]  122.55 49 0 top
PC1072  SC22U6D3V3MX-1-DL-GP  [C603H40]  147.21 33.62 0 bottom
PC1073  SC22U6D3V3MX-1-DL-GP  [C603H40]  121.28 49 0 top
PC1074  SC22U6D3V3MX-1-DL-GP  [C603H40]  149.75 33.62 0 bottom
PC1075  SC22U6D3V3MX-1-DL-GP  [C603H40]  119.22 48.98 0 top
PC1076  SC22U6D3V3MX-1-DL-GP  [C603H40]  145.31 32.73 90 bottom
PC1077  SC22U6D3V3MX-1-DL-GP  [C603H40]  145.31 31.46 90 bottom
PC1078  SC22U6D3V3MX-1-DL-GP  [C603H40]  148.48 33.62 0 bottom
PC1079  SC22U6D3V3MX-1-DL-GP  [C603H40]  143.78 49.74 270 top
PC1080  SC22U6D3V3MX-1-DL-GP  [C603H40]  143.78 48.47 270 top
PC1081  SC22U6D3V3MX-1-DL-GP  [C603H40]  143.78 45.93 270 top
PC1082  SC22U6D3V3MX-1-DL-GP  [C603H40]  143.78 43.39 270 top
PC1083  SC22U6D3V3MX-1-DL-GP  [C603H40]  143.78 42.12 270 top
PC1084  SC22U6D3V3MX-1-DL-GP  [C603H40]  143.78 40.85 270 top
PC1101  SC22U6D3V3MX-1-GP  [C603H40]  98.06 65.37 180 top
PC1102  SC22U6D3V3MX-1-GP  [C603H40]  80.28 10.76 0 top
PC1103  SC22U6D3V3MX-1-GP  [C603H40]  114.9 51.82 270 top
PC1104  SC22U6D3V3MX-1-GP  [C603H40]  79.01 10.76 0 top
PC1105  SC22U6D3V3MX-1-GP  [C603H40]  97.66 20.71 90 bottom
PC1106  SC22U6D3V3MX-1-GP  [C603H40]  97.66 19.44 90 bottom
PC1107  SC10U6D3V3MX-GP  [C603H38]  78.61 57.18 0 top
PC1108  SC10U6D3V3MX-GP  [C603H38]  77.28 57.18 0 top
PC1109  SC10U6D3V3MX-GP  [C603H38]  82.57 51.27 0 top
PC1110  SCD1U25V2KX-GP  [C402H22]  75.46 56.98 0 top
PC1111  SCD1U25V2KX-GP  [C402H22]  87.4 51.4 0 top
PC1112  SCD1U25V2KX-GP  [C402H22]  95.52 55.21 0 top
PC1113  SCD1U25V2KX-GP  [C402H22]  82.06 65.24 180 top
PC1114  SC22U6D3V3MX-1-GP  [C603H40]  83.21 65.37 180 top
PC1115  SC22U6D3V3MX-1-GP  [C603H40]  48.28 49.87 270 top
PC4301  SC1U50V3KX-1-GP  [C603H36]  19.45 88.1 0 top
PC4302  SCD1U50V3KX-DL-GP  [C603H35]  24.79 85.81 0 top
PC4303  SCD01U50V2KX-1DLGP  [C402H22]  18.94 80.73 270 top
PC4304  SCD01U50V2KX-1DLGP  [C402H22]  18.94 83.78 270 top
PC4305  SCD01U50V2KX-1DLGP  [C402H22]  18.94 84.54 270 top
PC4306  SC10U25V5KX-DL-GP  [C805H58]  18.57 82.03 270 top
PC4307  SC1KP50V2KX-1DLGP  [C402H22]  14.12 84.67 180 bottom
PC4310  SC100P50V2JN-3DLGP  [C402H22]  29.05 86.5 90 top
PC4311  SC100P50V2JN-3DLGP  [C402H22]  38.63 76.29 270 top
PC4312  SCD1U25V2KX-GP  [C402H22]  35.45 86.57 270 top
PC4313  SCD1U25V2KX-1-DL-GP  [C402H22]  34.56 75.4 90 top
PC4314  SC1U25V2KX-4-GP  [C402H22]  41.04 72.73 0 top
PC4315  SC100P50V2JN-3DLGP  [C402H22]  43.58 74.64 90 top
PC4401  SC10U25V5KX-DL-GP  [C805H58]  197.25 39.84 270 bottom
PC4402  SC10U25V5KX-DL-GP  [C805H58]  188.87 43.01 0 bottom
PC4403  SC10U25V5KX-DL-GP  [C805H58]  190.27 39.2 180 bottom
PC4404  SC10U25V5KX-DL-GP  [C805H58]  188.36 39.2 180 bottom
PC4405  SC10U25V5KX-DL-GP  [C805H58]  186.46 39.2 180 bottom
PC4406  SCD1U25V2KX-1-DL-GP  [C402H22]  186.2 33.62 0 bottom
PC4407  SC10U25V5KX-DL-GP  [C805H58]  184.93 25.87 180 bottom
PC4408  SC10U25V5KX-DL-GP  [C805H58]  190.65 25.87 180 bottom
PC4409  SC10U25V5KX-DL-GP  [C805H58]  192.37 33.74 0 bottom
PC4410  SC10U25V5KX-DL-GP  [C805H58]  188.74 25.87 180 bottom
PC4411  SC10U25V5KX-DL-GP  [C805H58]  188.77 33.74 0 bottom
PC4412  SC10U25V5KX-DL-GP  [C805H58]  183.03 25.87 180 bottom
PC4413  SC10U25V5KX-DL-GP  [C805H58]  190.57 33.74 0 bottom
PC4414  SC10U25V5KX-DL-GP  [C805H58]  186.84 25.87 180 bottom
PC4415  SC4D7U6D3V3KX-DLGP  [C603H36]  201.57 34.5 270 bottom
PC4416  SC1U50V3KX-1-GP  [C603H36]  203.47 35.77 180 bottom
PC4417  SC1U50V3KX-1-GP  [C603H36]  200.43 36.54 180 bottom
PC4419  SC1U50V3KX-1-GP  [C603H36]  203.09 32.35 0 bottom
PC4420  SCD1U25V2KX-1-DL-GP  [C402H22]  207.41 30.31 180 bottom
PC4421  SC4D7U6D3V3KX-DLGP  [C603H36]  194.97 31.96 90 bottom
PC4422  SC4D7U6D3V3KX-DLGP  [C603H36]  205.51 30.29 270 bottom
PC4423  SCD22U25V3KX-DL-GP  [C603H36]  194.71 30.69 270 bottom
PC4424  SC1U50V3KX-1-GP  [C603H36]  194.71 28.03 270 bottom
PC4425  SC1U50V3KX-1-GP  [C603H36]  196.74 27.27 180 bottom
PC4426  SC1U50V3KX-1-GP  [C603H36]  195.09 25.23 270 bottom
PC4427  SC10U25V5KX-DL-GP  [C805H58]  178.07 28.71 0 bottom
PC4428  SC10U25V5KX-DL-GP  [C805H58]  178.07 25.79 180 bottom
PC4429  SC4700P50V2KX-1DLGP  [C402H22]  176.8 23.94 270 bottom
PC4430  SC10P50V2JN-4DLGP  [C402H22]  199.79 23.46 180 bottom
PC4431  SCD01U50V2KX-1DLGP  [C402H22]  197.89 21.42 270 bottom
PC4432  SC1KP50V2KX-1DLGP  [C402H22]  196.36 21.42 90 bottom
PC4433  SC1KP50V2KX-1DLGP  [C402H22]  198.27 22.69 180 bottom
PC4435  SC1KP50V2KX-1DLGP  [C402H22]  182.77 40.73 0 top
PC4436  SCD22U25V3KX-DL-GP  [C603H36]  197.89 35.39 0 bottom
PC4438  SC1U10V2KX-1DLGP  [C402H22]  191.41 71.59 0 top
PC4439  SC1U50V3KX-1-GP  [C603H36]  187.22 33.74 180 bottom
PC4440  SC1U50V3KX-1-GP  [C603H36]  192.73 25.23 270 bottom
PC4441  SC22U25V5MX-5-GP  [C805H58]  124.99 100.42 180 bottom
PC4442  SC22U25V5MX-5-GP  [C805H58]  53.23 99.78 180 bottom
PC4443  SC22U25V5MX-5-GP  [C805H58]  190.85 29.81 270 bottom
PC4501  SCD1U25V2KX-1-DL-GP  [C402H22]  190.52 61.05 270 bottom
PC4502  SC10U25V5KX-DL-GP  [C805H58]  187.68 58.58 90 bottom
PC4503  SC10U25V5KX-DL-GP  [C805H58]  187.68 56.76 90 bottom
PC4504  SC10U25V5KX-DL-GP  [C805H58]  187.68 60.41 90 bottom
PC4505  SC10U25V5KX-DL-GP  [C805H58]  191.51 69.48 180 bottom
PC4506  SCD1U25V2KX-1-DL-GP  [C402H22]  187.22 53.81 0 bottom
PC4507  SC4D7U6D3V3KX-DLGP  [C603H36]  194.2 55.21 270 bottom
PC4508  SCD1U25V2KX-1-DL-GP  [C402H22]  194.46 59.52 270 bottom
PC4509  SC22U6D3V5MX-2DLGP  [C805H54]  190.77 44.54 180 bottom
PC4510  SC22U6D3V5MX-2DLGP  [C805H54]  192.68 44.54 180 bottom
PC4511  SC22U6D3V5MX-2DLGP  [C805H54]  188.36 47.33 90 bottom
PC4512  SC22U6D3V5MX-2DLGP  [C805H54]  193.82 51.14 0 bottom
PC4513  SCD1U25V2KX-1-DL-GP  [C402H22]  188.36 48.73 90 bottom
PC4514  SC22U6D3V5MX-2DLGP  [C805H54]  201.57 55.46 270 bottom
PC4515  SC22U6D3V5MX-2DLGP  [C805H54]  197.38 55.46 90 bottom
PC4516  SC22U6D3V5MX-2DLGP  [C805H54]  201.57 57.36 270 bottom
PC4517  SC22U6D3V5MX-2DLGP  [C805H54]  197.38 57.36 90 bottom
PC4518  SCD1U25V2KX-1-DL-GP  [C402H22]  197.25 58.71 90 bottom
PC4519  SC10U25V5KX-DL-GP  [C805H58]  189.71 69.48 180 bottom
PC4520  SC4D7U6D3V3KX-DLGP  [C603H36]  200.43 68.29 270 bottom
PC4521  SCD1U25V2KX-1-DL-GP  [C402H22]  195.35 65.37 0 bottom
PC4522  SCD1U25V2KX-1-DL-GP  [C402H22]  188.41 69.13 180 bottom
PC4523  SC10U25V5KX-DL-GP  [C805H58]  193.31 69.48 180 bottom
PC4524  SC2D2U10V3KX-1DLGP-U  [C603H36]  197.12 69.43 180 top
PC4525  SC22U6D3V5MX-2DLGP  [C805H54]  188.36 45.53 90 bottom
PC4526  SC1KP50V2KX-1DLGP  [C402H22]  199.79 71.67 270 bottom
PC4527  SC22U6D3V5MX-2DLGP  [C805H54]  201.57 53.55 270 bottom
PC4529  SC22U6D3V5MX-2DLGP  [C805H54]  197.38 53.55 90 bottom
PC4530  SCD1U25V2KX-1-DL-GP  [C402H22]  197.76 72.73 180 top
PC4531  SCD1U25V2KX-1-DL-GP  [C402H22]  199.28 70.95 180 top
PC4532  SCD1U25V2KX-1-DL-GP  [C402H22]  194.46 58.76 270 bottom
PC4533  SC1KP50V2KX-1DLGP  [C402H22]  194.71 56.98 270 bottom
PC4601  SC2200P50V2KX-2DLGP  [C402H22]  174.9 68.79 180 bottom
PC4602  SCD1U25V2KX-1-DL-GP  [C402H22]  184.55 59.65 90 top
PC4603  SCD1U25V2KX-1-DL-GP  [C402H22]  184.04 65.24 90 bottom
PC4604  SC330P50V2KX-3-DL-GP  [C402H22]  179.47 60.64 0 top
PC4605  SCD047U25V2KX-4-GP  [C402H22]  181.25 66.89 0 bottom
PC4606  SCD22U25V3KX-DL-GP  [C603H36]  184.42 64.73 90 top
PC4607  SC1U10V2KX-1DLGP  [C402H22]  181.12 62.06 270 top
PC4608  SCD022U16V2KX-3DLGP  [C402H22]  184.04 66.76 270 bottom
PC4609  SCD01U50V2KX-1DLGP  [C402H22]  177.82 54.95 180 bottom
PC4610  SC33P50V2JN-3DLGP  [C402H22]  179.67 57.85 90 top
PC4611  SC2200P50V2KX-2DLGP  [C402H22]  180.11 64.73 90 top
PC4612  SC2200P50V2KX-2DLGP  [C402H22]  184.32 56.48 270 bottom
PC4613  SCD01U50V2KX-1DLGP  [C402H22]  181.38 68.41 270 bottom
PC4614  SC330P50V2KX-3-DL-GP  [C402H22]  182.9 55.46 270 bottom
PC4615  SCD01U50V2KX-1DLGP  [C402H22]  182.52 54.32 180 bottom
PC4616  SC1KP50V2KX-1DLGP  [C402H22]  181 70.45 0 bottom
PC4617  SC1KP50V2KX-1DLGP  [C402H22]  179.22 72.73 270 bottom
PC4618  SC1KP50V2KX-1DLGP  [C402H22]  180.97 54.65 90 bottom
PC4619  SC1KP50V2KX-1DLGP  [C402H22]  180.03 55.69 90 bottom
PC4620  SCD01U50V2KX-1DLGP  [C402H22]  179.22 71.97 90 bottom
PC4621  SC680P50V2KX-2DLGP  [C402H22]  179.09 70.06 270 bottom
PC4622  SCD01U50V2KX-1DLGP  [C402H22]  178.2 59.4 90 top
PC4623  SC2200P50V2KX-2DLGP  [C402H22]  175.79 58.63 270 bottom
PC4624  SC33P50V2JN-3DLGP  [C402H22]  176.17 68.41 90 bottom
PC4625  SCD022U16V2KX-3GP  [C402H22]  174.01 55.21 0 bottom
PC4626  SCD022U16V2KX-3GP  [C402H22]  173.5 57.11 270 bottom
PC4628  SCD033U16V2KX-DLGP  [C402H22]  178.58 54.95 180 bottom
PC4629  SC330P50V2KX-3-DL-GP  [C402H22]  176.17 67.65 270 bottom
PC4630  SCD1U25V2KX-1-DL-GP  [C402H22]  178.07 56.86 90 bottom
PC4631  SCD1U25V2KX-1-DL-GP  [C402H22]  170.84 67.27 0 bottom
PC4632  SC2200P50V2KX-2DLGP  [C402H22]  173.01 67.67 270 bottom
PC4633  SCD1U25V2KX-1-DL-GP  [C402H22]  175.53 55.21 180 bottom
PC4634  SCD1U25V2KX-1-DL-GP  [C402H22]  173.01 66.15 270 bottom
PC4635  SCD01U50V2KX-1DLGP  [C402H22]  170.96 65.62 180 bottom
PC4637  SCD01U50V2KX-1DLGP  [C402H22]  171.98 63.84 0 bottom
PC4638  SC330P50V2KX-3-DL-GP  [C402H22]  171.74 57.89 90 bottom
PC4639  SC33P50V2JN-3DLGP  [C402H22]  171.72 60.29 90 bottom
PC4640  SC2200P50V2KX-2DLGP  [C402H22]  168.95 59.41 90 bottom
PC4641  SC330P50V2KX-3-DL-GP  [C402H22]  170.45 60.67 180 bottom
PC4642  SC1KP50V2KX-1DLGP  [C402H22]  169.16 63.46 90 bottom
PC4643  SC1KP50V2KX-1DLGP  [C402H22]  169.16 62.7 90 bottom
PC4644  SCD01U50V2KX-1DLGP  [C402H22]  169.57 61.43 180 bottom
PC4651  SC1KP50V2KX-1DLGP  [C402H22]  184.32 57.24 270 bottom
PC4652  SCD022U16V2KX-3DLGP  [C402H22]  170.2 65.62 180 bottom
PC4653  SCD047U25V2KX-4-GP  [C402H22]  177.06 54.95 180 bottom
PC4701  SC10U25V5KX-DL-GP  [C805H58]  161.69 54.82 0 bottom
PC4702  SC10U25V5KX-DL-GP  [C805H58]  163.6 54.82 0 bottom
PC4703  SC10U25V5KX-DL-GP  [C805H58]  165.5 54.82 0 bottom
PC4704  SC10U25V5KX-DL-GP  [C805H58]  159.79 54.82 0 bottom
PC4706  SC1KP50V2KX-1DLGP  [C402H22]  153.06 57.62 90 top
PC4707  SCD22U25V3KX-DL-GP  [C603H36]  155.85 53.4 0 bottom
PC4708  SC1U10V2KX-1DLGP  [C402H22]  152.55 58 180 bottom
PC4802  SC10U25V5KX-DL-GP  [C805H58]  166.14 42 0 bottom
PC4803  SC10U25V5KX-DL-GP  [C805H58]  167.91 38.06 180 bottom
PC4804  SC10U25V5KX-DL-GP  [C805H58]  164.23 42 0 bottom
PC4805  SC10U25V5KX-DL-GP  [C805H58]  168.04 42 0 bottom
PC4808  SCD22U25V3KX-DL-GP  [C603H36]  165.76 38.7 90 bottom
PC4809  SC1U10V2KX-1DLGP  [C402H22]  157.5 36.16 180 bottom
PC4810  SC1KP50V2KX-1DLGP  [C402H22]  159.41 42.89 180 top
PC4811  SCD22U25V3KX-DL-GP  [C603H36]  165.5 46.82 90 bottom
PC4812  SC1U10V2KX-1DLGP  [C402H22]  159.41 46.82 180 top
PC4813  SC1KP50V2KX-1DLGP  [C402H22]  159.28 50.63 180 top
PC4814  SC10U25V5KX-DL-GP  [C805H58]  164.1 50.13 0 bottom
PC4815  SC10U25V5KX-DL-GP  [C805H58]  167.66 47.08 180 bottom
PC4816  SC10U25V5KX-DL-GP  [C805H58]  167.71 50.13 0 bottom
PC4817  SC10U25V5KX-DL-GP  [C805H58]  165.91 50.13 0 bottom
PC5001  SC2D2U10V3KX-1DLGP-U  [C603H36]  165.37 28.79 90 bottom
PC5002  SC10U25V5KX-DL-GP  [C805H58]  166.52 31.96 180 bottom
PC5003  SC10U25V5KX-DL-GP  [C805H58]  164.61 31.96 180 bottom
PC5004  SCD1U25V2KX-1-DL-GP  [C402H22]  163.22 31.84 180 bottom
PC5005  SCD22U25V3KX-DL-GP  [C603H36]  169.31 32.35 90 bottom
PC5104  SC22U6D3V5MX-2DLGP  [C805H54]  35.2 97.24 90 bottom
PC5105  SC22U6D3V5MX-2DLGP  [C805H54]  34.69 95.34 90 bottom
PC5107  SC22U6D3V5MX-2DLGP  [C805H54]  39.77 95.21 270 bottom
PC5109  SC22U6D3V5MX-2DLGP  [C805H54]  39.77 97.12 270 bottom
PC5110  SC1U10V2KX-1DLGP  [C402H22]  42.44 95.97 180 bottom
PC5111  SC10U25V5KX-DL-GP  [C805H58]  51.2 100.93 180 bottom
PC5112  SC2D2U10V3KX-1DLGP-U  [C603H36]  41.17 99.91 180 top
PC5113  SC470P50V2KX-3DLGP  [C402H22]  43.96 95.97 0 bottom
PC5114  SCD1U25V2KX-1-DL-GP  [C402H22]  40.28 101.94 0 top
PC5115  SC10U25V5KX-DL-GP  [C805H58]  49.3 100.93 180 bottom
PC5116  SCD1U25V2KX-1-DL-GP  [C402H22]  47.9 101.05 180 bottom
PC5118  SCD1U25V2KX-1-DL-GP  [C402H22]  50.08 11.64 90 bottom
PC5119  SCD1U16V2KX-3DLGP  [C402H22]  60.85 13.04 270 bottom
PC5120  SCD1U16V2KX-3DLGP  [C402H22]  60.85 13.8 270 bottom
PC5121  SC1U10V2KX-1DLGP  [C402H22]  60.85 11.52 270 bottom
PC5122  SC10U6D3V3MX-DL-GP  [C603H36]  52.47 9.99 0 top
PC5123  SCD1U25V2KX-1-DL-GP  [C402H22]  57.42 15.33 90 bottom
PC5124  SC22U6D3V5MX-2DLGP  [C805H54]  52.34 14.18 0 bottom
PC5201  SC22U6D3V3MX-1-DL-GP  [C603H40]  105.23 6.95 90 bottom
PC5202  SC1U10V2KX-1DLGP  [C402H22]  115.21 8.72 0 bottom
PC5203  SC22U6D3V3MX-1-DL-GP  [C603H40]  105.23 5.68 90 bottom
PC5204  SCD1U25V2KX-1-DL-GP  [C402H22]  114.02 4.99 0 top
PC5205  SC22U6D3V3MX-1-DL-GP  [C603H40]  105.23 4.41 90 bottom
PC5206  SC22U6D3V3MX-1-DL-GP  [C603H40]  105.68 2.37 180 bottom
PC5208  SCD1U25V2KX-1-DL-GP  [C402H22]  104.8 7.96 90 bottom
PC5209  SC10U25V5KX-DL-GP  [C805H58]  122.73 4.3 180 bottom
PC5210  SC10U25V5KX-DL-GP  [C805H58]  121.66 8.24 0 bottom
PC5211  SC10U25V5KX-DL-GP  [C805H58]  125.27 8.24 0 bottom
PC5212  SC220P50V2KX-3DLGP  [C402H22]  119.15 10.37 270 bottom
PC5213  SCD01U50V2KX-1DLGP  [C402H22]  115.97 8.72 0 bottom
PC5214  SCD1U50V3KX-DL-GP  [C603H35]  121.18 4.28 180 bottom
PC5215  SC1KP50V2KX-1DLGP  [C402H22]  117.11 8.98 90 bottom
PC5216  SC10U25V5KX-DL-GP  [C805H58]  123.46 8.24 0 bottom
PC5401  SC1U10V2KX-1DLGP  [C402H22]  38.63 2.63 0 top
PC5402  SC10U6D3V3MX-DL-GP  [C603H36]  41.8 13.83 270 bottom
PC5403  SC10U6D3V3MX-DL-GP  [C603H36]  40.66 2.5 180 bottom
PC5404  SC22U6D3V5MX-2DLGP  [C805H54]  41.8 12.03 270 bottom
PC5405  SC68P50V2JN-1DLGP  [C402H22]  37.74 12.66 90 bottom
PC5406  SC4700P50V2KX-1DLGP  [C402H22]  35.45 2.63 180 bottom
PC5410  SC1U10V2KX-1DLGP  [C402H22]  44.85 2.75 0 top
PC5411  SC68P50V2JN-1DLGP  [C402H22]  44.22 11.52 90 bottom
PC5412  SC22U6D3V5MX-2DLGP  [C805H54]  47.39 12.15 270 bottom
PC5413  SC10U6D3V3MX-DL-GP  [C603H36]  47.26 13.8 270 bottom
PC5414  SC10U6D3V3MX-DL-GP  [C603H36]  46.12 2.75 180 bottom
PC5427  SCD1U25V2KX-1-DL-GP  [C402H22]  41.68 2.63 180 bottom
PC8201  SCD1U16V2KX-3DLGP  [C402H22]  135.4 123.91 0 top
PC8202  SCD1U25V2KX-1-DL-GP  [C402H22]  136.16 123.91 0 bottom
PC8203  SC1KP50V2KX-1DLGP  [C402H22]  132.35 123.91 180 bottom
PC8204  SCD01U50V2KX-1DLGP  [C402H22]  134.64 123.91 180 top
PC8205  SC47P50V2JN-5DLGP  [C402H22]  135.55 121.14 270 top
PC8206  SC330P50V2JN-1-DL-GP  [C402H22]  133.24 104.81 90 top
PC8207  SCD1U50V3KX-DL-GP  [C603H35]  134.03 116.04 180 bottom
PC8208  SC4D7U25V5KX-DL-GP  [C805H54]  123.72 111.47 90 bottom
PC8209  SC4D7U25V5KX-DL-GP  [C805H54]  129.69 113.37 270 bottom
PC8210  SC10U25V5KX-DL-GP  [C805H58]  144.42 109.31 270 bottom
PC8211  SCD1U50V3KX-DL-GP  [C603H35]  130.46 117.01 270 bottom
PC8212  SC4D7U25V5KX-DL-GP  [C805H54]  144.42 111.85 270 bottom
PC8213  SC4D7U25V5KX-DL-GP  [C805H54]  138.58 113.37 90 bottom
PC8214  SC10U25V5KX-DL-GP  [C805H58]  123.72 109.56 90 bottom
PC8215  SC10U25V5KX-DL-GP  [C805H58]  123.72 107.66 90 bottom
PC8216  SCD1U50V3KX-DL-GP  [C603H35]  139.47 117.31 90 bottom
PC8218  SC330P50V2JN-1-DL-GP  [C402H22]  134.77 104.81 270 top
PC8219  SC47P50V2JN-5DLGP  [C402H22]  137.94 122.77 0 bottom
PC8220  SCD1U25V2KX-1-DL-GP  [C402H22]  129.56 111.97 270 bottom
PC8221  SCD1U25V2KX-1-DL-GP  [C402H22]  138.58 111.97 90 bottom
PC8222  SC47P50V2JN-5DLGP  [C402H22]  138.7 121.88 180 bottom
PC8223  SC2700P50V2KX-1-DL-GP  [C402H22]  133.12 123.94 180 top
PC8224  SC10U25V5KX-DL-GP  [C805H58]  144.42 106.77 270 bottom
PC8225  SCD1U25V2KX-1-DL-GP  [C402H22]  126.77 118.2 90 bottom
PC8226  SCD1U25V2KX-1-DL-GP  [C402H22]  130.2 123.82 90 top
PC8301  SC1U10V2KX-1DLGP  [C402H22]  159.72 123.9 270 bottom
PC8302  SC22P50V2JN-4DLGP  [C402H22]  154.2 125.18 270 bottom
PC8303  SC22U6D3V3MX-1-DL-GP  [C603H40]  144.04 124.29 0 bottom
PC8304  SC22U6D3V3MX-1-DL-GP  [C603H40]  145.44 124.29 0 bottom
PC8306  SC10U6D3V3MX-DL-GP  [C603H36]  161.93 121.32 270 bottom
PC8307  SC10U6D3V3MX-DL-GP  [C603H36]  161.93 122.59 270 bottom
PC8308  SC330P50V2KX-3-DL-GP  [C402H22]  187.47 78.7 270 bottom
PC8309  SCD01U50V2KX-1DLGP  [C402H22]  196.36 80.86 270 bottom
PC8310  SC10U25V5KX-DL-GP  [C805H58]  196.36 79.46 270 bottom
PC8311  SC22U6D3V3MX-1-DL-GP  [C603H40]  189.76 90.26 90 bottom
PC8312  SC680P50V2KX-2DLGP  [C402H22]  158.01 124.17 90 top
PC8313  SC22U6D3V3MX-1-DL-GP  [C603H40]  189.76 91.53 90 bottom
PC8314  SCD1U25V2KX-1-DL-GP  [C402H22]  189.5 92.54 90 bottom
PC8315  SC10U25V5KX-DL-GP  [C805H58]  196.36 77.56 270 bottom
PC8316  SCD1U16V2KX-3DLGP  [C402H22]  189.38 75.91 180 bottom
PC8317  SC2D2U10V3KX-1DLGP-U  [C603H36]  190.01 83.15 90 bottom
PC8318  SC1U10V2KX-1DLGP  [C402H22]  188.87 81.11 90 bottom
PC8319  SCD1U25V2KX-1-DL-GP  [C402H22]  194.2 83.15 90 bottom
PC8320  SC22U6D3V3MX-1-DL-GP  [C603H40]  193.57 91.53 270 bottom
PC8321  SC22U6D3V3MX-1-DL-GP  [C603H40]  193.57 90.26 270 bottom
PC8322  SC47P50V2JN-5DLGP  [C402H22]  138.7 123.53 0 bottom
PC8323  SC22P50V2JN-4DLGP  [C402H22]  158.14 125.06 90 bottom
PD4301  P6SMB27A-GP  [DO214AAAKH97]  20.09 86.32 0 bottom
PD4302  LBAV99LT1G-1-GP  [SOT23-2D4-312H44]  56.66 96.86 0 bottom
PD4303  L30ESD24VC3-2-GP  [SOT23-2D4-312H60]  56.66 100.04 180 bottom
PD4304  SMF18A-GP  [SOD123AK-2H43]  174.65 29.45 90 bottom
PD4305  RB751V-40-2-GP  [SOD323AKH38]  37.49 81.49 270 top
PD4306  RB751V-40H-GP  [SOD323AKH38]  33.8 81.49 90 top
PD4307  RB751V-40H-GP  [SOD323AKH38]  42.57 87.46 90 top
PD4308  RB751V-40H-GP  [SOD323AKH38]  42.57 85.69 90 top
PD4309  RB751V-40H-GP  [SOD323AKH38]  44.34 46.95 270 top
PD4310  RB751V-40H-GP  [SOD323AKH38]  44.34 48.86 270 top
PD4401  BAT54C-12-GP  [SOT-23-9H44]  212.49 31.2 180 bottom
PD4404  L1SS355T1G-GP  [SOD323AKH44]  190.01 64.6 270 top
PD4407  RB751V-40H-GP  [SOD323AKH38]  209.7 31.08 0 bottom
PD4408  BAT54C-12-GP  [SOT-23-9H44]  212.36 27.39 90 bottom
PG4401  GAP-CLOSE-PWR-3-GP  [GAP-CLOSE-PWR-3]  194.58 40.09 270 bottom
PG4402  GAP-CLOSE-PWR-3-GP  [GAP-CLOSE-PWR-3]  191.79 40.09 270 bottom
PG4405  GAP-CLOSE-PWR-3-GP  [GAP-CLOSE-PWR-3]  181.38 24.85 270 bottom
PG4406  GAP-CLOSE-PWR-3-GP  [GAP-CLOSE-PWR-3]  179.6 24.85 270 bottom
PG4408  GAP-CLOSE-PWR-3-GP  [GAP-CLOSE-PWR-3]  205.13 28.15 0 bottom
PG4501  GAP-CLOSE-PWR-3-GP  [GAP-CLOSE-PWR-3]  193.57 72.1 270 bottom
PG4502  GAP-CLOSE-PWR-3-GP  [GAP-CLOSE-PWR-3]  191.28 72.1 270 bottom
PG4503  GAP-CLOSE-PWR-3-GP  [GAP-CLOSE-PWR-3]  192.81 72.1 270 bottom
PG4504  GAP-CLOSE-PWR-3-GP  [GAP-CLOSE-PWR-3]  190.52 72.1 270 bottom
PG4505  GAP-CLOSE-PWR-3-GP  [GAP-CLOSE-PWR-3]  189.76 72.1 270 bottom
PG4506  GAP-CLOSE-PWR-3-GP  [GAP-CLOSE-PWR-3]  192.04 72.1 270 bottom
PG4507  GAP-CLOSE-PWR-3-GP  [GAP-CLOSE-PWR-3]  198.78 51.9 270 bottom
PG4508  GAP-CLOSE-PWR-3-GP  [GAP-CLOSE-PWR-3]  199.03 52.92 270 top
PG4509  GAP-CLOSE-PWR-3-GP  [GAP-CLOSE-PWR-3]  199.79 52.92 270 top
PG4510  GAP-CLOSE-PWR-3-GP  [GAP-CLOSE-PWR-3]  200.3 51.9 270 bottom
PG4511  GAP-CLOSE-PWR-3-GP  [GAP-CLOSE-PWR-3]  200.55 52.92 270 top
PG4512  GAP-CLOSE-PWR-3-GP  [GAP-CLOSE-PWR-3]  198.27 52.92 270 top
PG4513  GAP-CLOSE-PWR-3-GP  [GAP-CLOSE-PWR-3]  198.01 51.9 270 bottom
PG4514  GAP-CLOSE-PWR-3-GP  [GAP-CLOSE-PWR-3]  199.54 51.9 270 bottom
PG4515  GAP-CLOSE-PWR-3-GP  [GAP-CLOSE-PWR-3]  190.01 62.19 270 bottom
PG4516  GAP-CLOSE-PWR-3-GP  [GAP-CLOSE-PWR-3]  189.25 62.19 270 bottom
PG4517  GAP-CLOSE-PWR-3-GP  [GAP-CLOSE-PWR-3]  187.73 62.19 270 bottom
PG4518  GAP-CLOSE-PWR-3-GP  [GAP-CLOSE-PWR-3]  188.49 62.19 270 bottom
PG4519  GAP-CLOSE-PWR-3-GP  [GAP-CLOSE-PWR-3]  194.33 45.3 0 bottom
PG4520  GAP-CLOSE-PWR-3-GP  [GAP-CLOSE-PWR-3]  194.33 46.06 0 bottom
PG4521  GAP-CLOSE-PWR-3-GP  [GAP-CLOSE-PWR-3]  194.33 46.82 0 bottom
PG4522  GAP-CLOSE-PWR-3-GP  [GAP-CLOSE-PWR-3]  194.33 47.59 0 bottom
PG4523  GAP-CLOSE-PWR-3-GP  [GAP-CLOSE-PWR-3]  194.33 49.11 0 bottom
PG4524  GAP-CLOSE-PWR-3-GP  [GAP-CLOSE-PWR-3]  194.33 48.35 0 bottom
PG4527  GAP-CLOSE-PWR-3-GP  [GAP-CLOSE-PWR-3]  202.08 52.16 180 bottom
PG4528  GAP-CLOSE-PWR-3-GP  [GAP-CLOSE-PWR-3]  199.66 69.68 0 bottom
PG4529  GAP-CLOSE-PWR-3-GP  [GAP-CLOSE-PWR-3]  196.97 73.19 270 bottom
PG4530  GAP-CLOSE-PWR-3-GP  [GAP-CLOSE-PWR-3]  194.33 44.28 180 bottom
PG4531  GAP-CLOSE-PWR-3-GP  [GAP-CLOSE-PWR-3]  192.68 61.17 270 bottom
PG4532  GAP-CLOSE-PWR-3-GP  [GAP-CLOSE-PWR-3]  194.2 53.94 0 bottom
PG4701  GAP-CLOSE-PWR-3-GP  [GAP-CLOSE-PWR-3]  167.15 54.44 180 bottom
PG4702  GAP-CLOSE-PWR-3-GP  [GAP-CLOSE-PWR-3]  167.15 53.68 180 bottom
PG4703  GAP-CLOSE-PWR-3-GP  [GAP-CLOSE-PWR-3]  167.15 52.92 180 bottom
PG4704  GAP-CLOSE-PWR-3-GP  [GAP-CLOSE-PWR-3]  167.15 52.92 180 top
PG4705  GAP-CLOSE-PWR-3-GP  [GAP-CLOSE-PWR-3]  167.15 53.68 180 top
PG4706  GAP-CLOSE-PWR-3-GP  [GAP-CLOSE-PWR-3]  167.15 54.44 180 top
PG4707  GAP-CLOSE-PWR-3-GP  [GAP-CLOSE-PWR-3]  155.21 62.44 0 bottom
PG4708  GAP-CLOSE-PWR-3-GP  [GAP-CLOSE-PWR-3]  152.93 62.44 180 bottom
PG4802  GAP-CLOSE-PWR-3-GP  [GAP-CLOSE-PWR-3]  169.69 41.36 0 bottom
PG4803  GAP-CLOSE-PWR-3-GP  [GAP-CLOSE-PWR-3]  169.69 40.6 0 bottom
PG4804  GAP-CLOSE-PWR-3-GP  [GAP-CLOSE-PWR-3]  169.69 39.84 0 bottom
PG4805  GAP-CLOSE-PWR-3-GP  [GAP-CLOSE-PWR-3]  169.69 39.08 0 bottom
PG4806  GAP-CLOSE-PWR-3-GP  [GAP-CLOSE-PWR-3]  169.69 38.31 0 bottom
PG4808  GAP-CLOSE-PWR-3-GP  [GAP-CLOSE-PWR-3]  155.47 40.6 0 bottom
PG4809  GAP-CLOSE-PWR-3-GP  [GAP-CLOSE-PWR-3]  153.18 40.6 180 bottom
PG4810  GAP-CLOSE-PWR-3-GP  [GAP-CLOSE-PWR-3]  169.18 51.4 90 bottom
PG4811  GAP-CLOSE-PWR-3-GP  [GAP-CLOSE-PWR-3]  169.69 50.38 0 bottom
PG4812  GAP-CLOSE-PWR-3-GP  [GAP-CLOSE-PWR-3]  169.69 48.09 0 bottom
PG4813  GAP-CLOSE-PWR-3-GP  [GAP-CLOSE-PWR-3]  155.47 48.6 0 bottom
PG4814  GAP-CLOSE-PWR-3-GP  [GAP-CLOSE-PWR-3]  169.69 49.62 0 bottom
PG4815  GAP-CLOSE-PWR-3-GP  [GAP-CLOSE-PWR-3]  153.18 48.6 180 bottom
PG4816  GAP-CLOSE-PWR-3-GP  [GAP-CLOSE-PWR-3]  169.69 48.86 0 bottom
PG5001  GAP-CLOSE-PWR-3-GP  [GAP-CLOSE-PWR-3]  153.44 31.71 180 bottom
PG5002  GAP-CLOSE-PWR-3-GP  [GAP-CLOSE-PWR-3]  167.41 34 0 bottom
PG5003  GAP-CLOSE-PWR-3-GP  [GAP-CLOSE-PWR-3]  167.41 34.76 0 bottom
PG5011  GAP-CLOSE-PWR-3-GP  [GAP-CLOSE-PWR-3]  155.72 31.71 0 bottom
PG5105  GAP-CLOSE-PWR-3-GP  [GAP-CLOSE-PWR-3]  52.85 102.7 180 bottom
PG5106  GAP-CLOSE-PWR-3-GP  [GAP-CLOSE-PWR-3]  37.74 93.56 270 bottom
PG5107  GAP-CLOSE-PWR-3-GP  [GAP-CLOSE-PWR-3]  38.5 93.56 270 bottom
PG5108  GAP-CLOSE-PWR-3-GP  [GAP-CLOSE-PWR-3]  36.98 93.56 270 bottom
PG5109  GAP-CLOSE-PWR-3-GP  [GAP-CLOSE-PWR-3]  39.26 93.56 270 bottom
PG5110  GAP-CLOSE-PWR-3-GP  [GAP-CLOSE-PWR-3]  52.85 101.94 180 bottom
PG5111  GAP-CLOSE-PWR-3-GP  [GAP-CLOSE-PWR-3]  36.22 93.56 270 bottom
PG5112  GAP-CLOSE-PWR-3-GP  [GAP-CLOSE-PWR-3]  46.38 96.1 90 bottom
PG5113  GAP-CLOSE-PWR-3-GP  [GAP-CLOSE-PWR-3]  44.09 94.45 270 bottom
PG5114  GAP-CLOSE-PWR-3-GP  [GAP-CLOSE-PWR-3]  47.39 96.1 90 bottom
PG5115  GAP-CLOSE-PWR-3-GP  [GAP-CLOSE-PWR-3]  35.45 93.56 270 bottom
PG5120  GAP-CLOSE-PWR-3-GP  [GAP-CLOSE-PWR-3]  50.95 14.44 90 bottom
PG5121  GAP-CLOSE-PWR-3-GP  [GAP-CLOSE-PWR-3]  50.19 14.44 90 bottom
